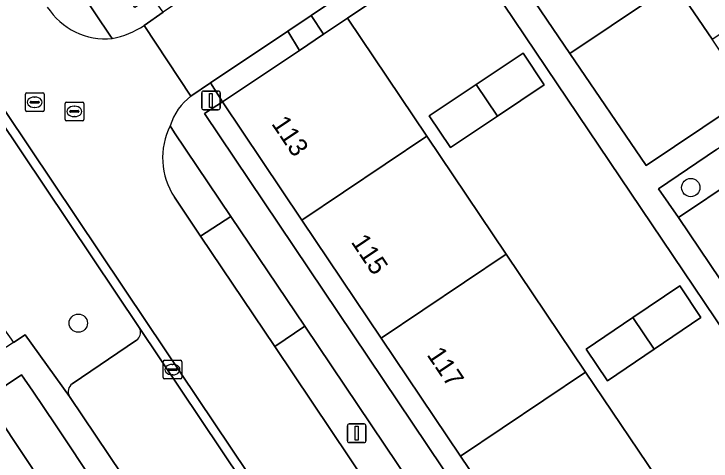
# Model space of a CAD drawing. Extents: x 158793 to 159888, y 384317 to 385256.
# Drawn here: x 159136.27 to 159173.56, y 384652.42 to 384676.36 of the extents above; entities that cross this region are included whole.
import ezdxf

# ---------------------------------------------------------------- set-up
doc = ezdxf.new("R2010")
doc.units = 0
for name, color, linetype in [('IMGEO_Berm_groen', 7, 'Continuous'), ('IMGEO_Boom', 7, 'Continuous'), ('IMGEO_Erf', 7, 'Continuous'), ('IMGEO_Groenvoorziening', 7, 'Continuous'), ('IMGEO_Kolk', 7, 'Continuous'), ('IMGEO_Lichtmast', 7, 'Continuous'), ('IMGEO_Pand', 7, 'Continuous'), ('IMGEO_Pand_nummerreeks', 7, 'Continuous'), ('IMGEO_Parkeervlak_halfverhard', 7, 'Continuous'), ('IMGEO_Parkeervlak_open', 7, 'Continuous'), ('IMGEO_Rijbaan_lokaal_open', 7, 'Continuous'), ('IMGEO_Rioolput', 7, 'Continuous'), ('IMGEO_Voetpad_open', 7, 'Continuous')]:
    doc.layers.add(name, color=color, linetype=linetype)

msp = doc.modelspace()

# ---------------------------------------------------------------- linework, layer by layer
at = {"layer": 'IMGEO_Berm_groen'}
for points in [[(159141.53, 384675.048), (159141.397, 384675.222), (159125.586, 384698.761)], [(159127.995, 384675.679), (159126.599, 384674.78), (159125.549, 384674.076), (159126.206, 384673.075), (159128.775, 384674.779), (159130.148, 384672.707), (159127.589, 384671.004), (159136.246, 384658.77), (159136.871, 384659.186), (159139.241, 384655.885)], [(159143.015, 384659.487), (159142.977, 384659.569), (159132.904, 384674.594)], [(159144.861, 384670.004), (159144.633, 384670.379)], [(159144.859, 384666.556), (159146.259, 384664.469), (159147.882, 384665.51), (159144.861, 384670.004)], [(159151.826, 384659.643), (159150.227, 384658.552), (159167.157, 384633.31)], [(159170.662, 384631.666), (159170.315, 384632.138), (159151.826, 384659.643)], [(159139.387, 384656.562), (159142.831, 384658.894)]]:
    msp.add_lwpolyline(points, dxfattribs=at)
for centre, radius, start, end in [((159141.175, 384678.74), 3.709, 212.7786, 275.4984), ((159148.052, 384668.663), 3.826, 153.3489, 213.4175), ((159142.536, 384659.311), 0.51, 305.2924, 20.2307), ((159139.7, 384656.14), 0.525, 126.5692, 209.091)]:
    msp.add_arc(centre, radius, start, end, dxfattribs=at)
at = {"layer": 'IMGEO_Boom'}
for centre in [(159172.479, 384667.067), (159139.714, 384659.808)]:
    msp.add_circle(centre, 0.489, dxfattribs=at)
at = {"layer": 'IMGEO_Erf'}
for points in [[(159193.99, 384675.621), (159189.711, 384681.984), (159196.396, 384686.477), (159192.579, 384692.111), (159185.929, 384687.638), (159179.282, 384683.167), (159172.635, 384678.697), (159166.005, 384674.237), (159170.09, 384668.243), (159183.846, 384677.493), (159200.696, 384652.438), (159206.826, 384656.531), (159202.548, 384662.893), (159198.269, 384669.257)], [(159160.216, 384680.233), (159154.114, 384676.135), (159158.36, 384669.818), (159162.607, 384663.5), (159166.854, 384657.182), (159171.101, 384650.864), (159175.348, 384644.546), (159179.596, 384638.227), (159185.666, 384642.429)], [(159176.993, 384673.63), (159175.3, 384672.493), (159173.617, 384675.003), (159171.935, 384677.512), (159173.629, 384678.648), (159175.311, 384676.139)], [(159162.134, 384670.885), (159159.624, 384669.204), (159158.489, 384670.899), (159160.999, 384672.58), (159163.508, 384674.261), (159164.643, 384672.566)], [(159168.023, 384656.723), (159166.88, 384658.408), (159169.384, 384660.105), (159171.887, 384661.802), (159173.015, 384660.108), (159170.526, 384658.42)]]:
    msp.add_lwpolyline(points, close=True, dxfattribs=at)
msp.add_lwpolyline([(159118.838, 384624.921), (159110.182, 384637.924), (159135.451, 384654.745), (159139.092, 384649.275), (159139.909, 384649.828), (159141.021, 384650.58), (159140.693, 384651.069), (159138.492, 384654.363), (159137.276, 384656.161), (159136.677, 384657.042), (159107.897, 384637.647), (159125.656, 384610.969)], dxfattribs=at)
at = {"layer": 'IMGEO_Groenvoorziening'}
for points in [[(159160.216, 384680.233), (159159.55, 384681.239), (159152.18, 384676.285), (159152.829, 384675.272), (159154.114, 384676.135)], [(159151.548, 384674.412), (159150.917, 384675.437), (159146.794, 384672.665), (159147.433, 384671.648)]]:
    msp.add_lwpolyline(points, close=True, dxfattribs=at)
msp.add_lwpolyline([(159173.849, 384669.112), (159170.75, 384666.999), (159171.817, 384665.462), (159174.9, 384667.527)], dxfattribs=at)
at = {"layer": 'IMGEO_Kolk'}
for p, q in [((159144.254, 384656.893), (159144.254, 384657.745)), ((159144.329, 384657.819), (159145.181, 384657.819)), ((159145.255, 384657.745), (159145.255, 384656.893)), ((159144.513, 384657.313), (159144.513, 384657.325)), ((159144.951, 384657.276), (159144.553, 384657.276)), ((159144.556, 384657.362), (159144.954, 384657.362)), ((159144.742, 384657.599), (159144.767, 384657.599)), ((159144.997, 384657.325), (159144.997, 384657.313)), ((159144.765, 384657.039), (159144.74, 384657.039)), ((159145.181, 384656.819), (159144.329, 384656.819))]:
    msp.add_line(p, q, dxfattribs=at)
for points in [[(159144.254, 384656.893), (159144.254, 384657.745)], [(159144.329, 384657.819), (159145.181, 384657.819)], [(159145.255, 384657.745), (159145.255, 384656.893)], [(159145.181, 384656.819), (159144.329, 384656.819)]]:
    msp.add_lwpolyline(points, dxfattribs=at)
for centre, radius, start, end in [((159144.331, 384657.743), 0.0765, 91.552, 178.448), ((159144.331, 384657.743), 0.0765, 91.552, 178.448), ((159145.179, 384657.743), 0.0765, 1.552, 88.448), ((159145.179, 384657.743), 0.0765, 1.552, 88.448), ((159144.553, 384657.322), 0.0403, 85.8775, 175.7526), ((159144.55, 384657.312), 0.0366, 178.938, 274.7102), ((159144.954, 384657.319), 0.043, 264.8664, 352.4533), ((159144.958, 384657.324), 0.0386, 1.7309, 96.639), ((159144.331, 384656.895), 0.0765, 181.552, 268.448), ((159144.331, 384656.895), 0.0765, 181.552, 268.448), ((159145.179, 384656.895), 0.0765, 271.552, 358.448), ((159145.179, 384656.895), 0.0765, 271.552, 358.448)]:
    msp.add_arc(centre, radius, start, end, dxfattribs=at)
for centre, major_axis, ratio, start_param, end_param in [((159144.741, 384657.319), (-0.387, 0.002), 0.722429, 4.712389, 7.853982), ((159144.766, 384657.319), (-0.39, 0.002), 0.717154, 1.570796, 4.712389)]:
    msp.add_ellipse(centre, major_axis=major_axis, ratio=ratio, start_param=start_param, end_param=end_param, dxfattribs=at)
at = {"layer": 'IMGEO_Lichtmast'}
for p, q in [((159146.416, 384672.232), (159147.206, 384672.232)), ((159147.206, 384672.232), (159146.416, 384672.232)), ((159146.316, 384671.332), (159146.316, 384672.132)), ((159146.316, 384672.132), (159146.316, 384671.332)), ((159147.306, 384672.132), (159147.306, 384671.332)), ((159147.306, 384671.332), (159147.306, 384672.132)), ((159147.206, 384671.232), (159146.416, 384671.232)), ((159146.416, 384671.232), (159147.206, 384671.232)), ((159154.113, 384653.512), (159154.113, 384654.312)), ((159154.113, 384654.312), (159154.113, 384653.512)), ((159154.213, 384654.412), (159155.003, 384654.412)), ((159155.003, 384654.412), (159154.213, 384654.412)), ((159155.103, 384654.312), (159155.103, 384653.512)), ((159155.103, 384653.512), (159155.103, 384654.312)), ((159155.003, 384653.412), (159154.213, 384653.412)), ((159154.213, 384653.412), (159155.003, 384653.412))]:
    msp.add_line(p, q, dxfattribs=at)
for points in [[(159146.736, 384672.107), (159146.886, 384672.107), (159146.886, 384671.357), (159146.736, 384671.357), (159146.736, 384672.107)], [(159154.533, 384654.287), (159154.683, 384654.287), (159154.683, 384653.537), (159154.533, 384653.537), (159154.533, 384654.287)]]:
    msp.add_lwpolyline(points, dxfattribs=at)
for centre, start, end in [((159146.416, 384672.132), 90, 180), ((159146.416, 384672.132), 90, 180), ((159147.206, 384672.132), 0, 90), ((159147.206, 384672.132), 360, 90), ((159146.416, 384671.332), 180, 270), ((159146.416, 384671.332), 180, 270), ((159147.206, 384671.332), 270, 0), ((159147.206, 384671.332), 270, 0), ((159154.213, 384654.312), 90, 180), ((159154.213, 384654.312), 90, 180), ((159155.003, 384654.312), 0, 90), ((159155.003, 384654.312), 360, 90), ((159154.213, 384653.512), 180, 270), ((159154.213, 384653.512), 180, 270), ((159155.003, 384653.512), 270, 0), ((159155.003, 384653.512), 270, 0)]:
    msp.add_arc(centre, 0.1, start, end, dxfattribs=at)
at = {"layer": 'IMGEO_Pand'}
for points in [[(159168.046, 384685.528), (159161.396, 384681.061), (159166.005, 384674.237), (159172.635, 384678.697)], [(159173.629, 384678.648), (159171.935, 384677.512), (159173.617, 384675.003), (159175.311, 384676.139)], [(159154.114, 384676.135), (159152.829, 384675.272), (159151.548, 384674.412), (159147.433, 384671.648), (159151.678, 384665.329), (159158.36, 384669.818)], [(159164.643, 384672.566), (159163.508, 384674.261), (159160.999, 384672.58), (159162.134, 384670.885)], [(159162.134, 384670.885), (159160.999, 384672.58), (159158.489, 384670.899), (159159.624, 384669.204)], [(159158.36, 384669.818), (159151.678, 384665.329), (159155.924, 384659.01), (159162.607, 384663.5)], [(159162.607, 384663.5), (159155.924, 384659.01), (159160.169, 384652.691), (159166.854, 384657.182)], [(159171.887, 384661.802), (159169.384, 384660.105), (159170.526, 384658.42), (159173.015, 384660.108)], [(159169.384, 384660.105), (159166.88, 384658.408), (159168.023, 384656.723), (159170.526, 384658.42)], [(159166.854, 384657.182), (159160.169, 384652.691), (159164.414, 384646.371), (159171.101, 384650.864)], [(159144.107, 384641.742), (159140.454, 384647.229), (159139.092, 384649.275), (159135.451, 384654.745), (159110.182, 384637.924), (159118.838, 384624.921)]]:
    msp.add_lwpolyline(points, close=True, dxfattribs=at)
at = {"layer": 'IMGEO_Parkeervlak_halfverhard'}
msp.add_lwpolyline([(159147.882, 384665.51), (159146.259, 384664.469), (159150.227, 384658.552), (159151.826, 384659.643)], close=True, dxfattribs=at)
at = {"layer": 'IMGEO_Parkeervlak_open'}
for points in [[(159174.9, 384667.527), (159171.817, 384665.462), (159179.041, 384654.743), (159182.119, 384656.825)], [(159142.977, 384659.569), (159143.015, 384659.487)], [(159151.786, 384646.421), (159142.977, 384659.569)], [(159142.831, 384658.894), (159139.387, 384656.562)], [(159139.241, 384655.885), (159146.994, 384644.33)]]:
    msp.add_lwpolyline(points, dxfattribs=at)
for centre, radius, start, end in [((159142.536, 384659.311), 0.51, 305.2924, 20.2307), ((159139.7, 384656.14), 0.525, 126.5692, 209.091)]:
    msp.add_arc(centre, radius, start, end, dxfattribs=at)
at = {"layer": 'IMGEO_Rijbaan_lokaal_open'}
for points in [[(159161.494, 384687.533), (159158.406, 384685.425), (159158.127, 384685.847), (159156.889, 384685.009), (159149.027, 384679.686), (159147.747, 384678.819), (159144.25, 384676.451), (159143.234, 384675.735), (159145.743, 384671.966), (159146.794, 384672.665), (159150.917, 384675.437), (159152.18, 384676.285), (159159.55, 384681.239), (159187.338, 384699.918), (159184.8, 384703.767), (159172.11, 384695.307), (159170.84, 384694.46), (159171.159, 384693.985), (159168.011, 384691.91)], [(159145.743, 384671.966), (159143.234, 384675.735)], [(159169.474, 384620.932), (159143.376, 384659.836), (159133.301, 384674.864)], [(159133.301, 384674.864), (159143.376, 384659.836), (159169.474, 384620.932)], [(159132.904, 384674.594), (159142.977, 384659.569), (159151.786, 384646.421), (159151.816, 384646.386), (159153.659, 384643.618), (159153.675, 384643.594), (159162.493, 384630.457), (159163.415, 384629.083), (159169.136, 384620.552)], [(159167.157, 384633.31), (159150.227, 384658.552), (159146.259, 384664.469), (159144.859, 384666.556)]]:
    msp.add_lwpolyline(points, dxfattribs=at)
for centre, radius, start, end in [((159141.175, 384678.74), 3.709, 212.7786, 275.4984), ((159140.604, 384679.802), 4.843, 281.0239, 302.8917), ((159147.74, 384669.387), 3.262, 127.7599, 162.2996), ((159148.052, 384668.663), 3.826, 153.3489, 213.4175)]:
    msp.add_arc(centre, radius, start, end, dxfattribs=at)
at = {"layer": 'IMGEO_Rioolput'}
for p, q in [((159136.885, 384671.207), (159136.885, 384672.059)), ((159136.96, 384672.133), (159137.812, 384672.133)), ((159137.373, 384671.913), (159137.398, 384671.913)), ((159137.886, 384672.059), (159137.886, 384671.207)), ((159137.144, 384671.627), (159137.144, 384671.639)), ((159137.582, 384671.59), (159137.184, 384671.59)), ((159137.187, 384671.676), (159137.585, 384671.676)), ((159137.628, 384671.639), (159137.628, 384671.627)), ((159139.007, 384670.716), (159139.007, 384671.568)), ((159139.082, 384671.642), (159139.934, 384671.642)), ((159140.008, 384671.568), (159140.008, 384670.716)), ((159137.812, 384671.133), (159136.96, 384671.133)), ((159137.396, 384671.353), (159137.371, 384671.353)), ((159139.266, 384671.136), (159139.266, 384671.148)), ((159139.704, 384671.099), (159139.306, 384671.099)), ((159139.309, 384671.185), (159139.707, 384671.185)), ((159139.495, 384671.422), (159139.52, 384671.422)), ((159139.75, 384671.148), (159139.75, 384671.136)), ((159139.518, 384670.862), (159139.493, 384670.862)), ((159139.934, 384670.642), (159139.082, 384670.642))]:
    msp.add_line(p, q, dxfattribs=at)
for points in [[(159136.885, 384671.207), (159136.885, 384672.059)], [(159136.96, 384672.133), (159137.812, 384672.133)], [(159137.886, 384672.059), (159137.886, 384671.207)], [(159139.007, 384670.716), (159139.007, 384671.568)], [(159139.082, 384671.642), (159139.934, 384671.642)], [(159140.008, 384671.568), (159140.008, 384670.716)], [(159137.812, 384671.133), (159136.96, 384671.133)], [(159139.934, 384670.642), (159139.082, 384670.642)]]:
    msp.add_lwpolyline(points, dxfattribs=at)
for centre, radius, start, end in [((159136.962, 384672.057), 0.0765, 91.552, 178.448), ((159136.962, 384672.057), 0.0765, 91.552, 178.448), ((159137.81, 384672.057), 0.0765, 1.552, 88.448), ((159137.81, 384672.057), 0.0765, 1.552, 88.448), ((159137.184, 384671.636), 0.0403, 85.8775, 175.7526), ((159137.181, 384671.626), 0.0366, 178.938, 274.7102), ((159137.585, 384671.633), 0.043, 264.8664, 352.4533), ((159137.589, 384671.638), 0.0386, 1.7309, 96.639), ((159139.084, 384671.566), 0.0765, 91.552, 178.448), ((159139.084, 384671.566), 0.0765, 91.552, 178.448), ((159139.932, 384671.566), 0.0765, 1.552, 88.448), ((159139.932, 384671.566), 0.0765, 1.552, 88.448), ((159136.962, 384671.209), 0.0765, 181.552, 268.448), ((159136.962, 384671.209), 0.0765, 181.552, 268.448), ((159137.81, 384671.209), 0.0765, 271.552, 358.448), ((159137.81, 384671.209), 0.0765, 271.552, 358.448), ((159139.306, 384671.145), 0.0403, 85.8775, 175.7526), ((159139.303, 384671.135), 0.0366, 178.938, 274.7102), ((159139.707, 384671.142), 0.043, 264.8664, 352.4533), ((159139.711, 384671.147), 0.0386, 1.7309, 96.639), ((159139.084, 384670.718), 0.0765, 181.552, 268.448), ((159139.084, 384670.718), 0.0765, 181.552, 268.448), ((159139.932, 384670.718), 0.0765, 271.552, 358.448), ((159139.932, 384670.718), 0.0765, 271.552, 358.448)]:
    msp.add_arc(centre, radius, start, end, dxfattribs=at)
for centre, major_axis, ratio, start_param, end_param in [((159137.372, 384671.633), (-0.387, 0.002), 0.722429, 4.712389, 7.853982), ((159137.397, 384671.633), (-0.39, 0.002), 0.717154, 1.570796, 4.712389), ((159139.494, 384671.142), (-0.387, 0.002), 0.722429, 4.712389, 7.853982), ((159139.519, 384671.142), (-0.39, 0.002), 0.717154, 1.570796, 4.712389)]:
    msp.add_ellipse(centre, major_axis=major_axis, ratio=ratio, start_param=start_param, end_param=end_param, dxfattribs=at)
at = {"layer": 'IMGEO_Voetpad_open'}
for points in [[(159143.234, 384675.735), (159144.25, 384676.451), (159143.648, 384677.306), (159142.742, 384676.698), (159117.11, 384714.557)], [(159113.6, 384713.295), (159115.157, 384714.276), (159117.976, 384710.09), (159121.876, 384704.284), (159125.586, 384698.761), (159141.397, 384675.222), (159141.53, 384675.048)], [(159200.696, 384652.438), (159183.846, 384677.493), (159170.09, 384668.243), (159166.005, 384674.237), (159161.396, 384681.061)], [(159160.216, 384680.233), (159185.666, 384642.429), (159186.31, 384641.472), (159187.415, 384642.245), (159185.923, 384644.473), (159180.087, 384653.183), (159179.041, 384654.743), (159171.817, 384665.462), (159170.75, 384666.999), (159173.849, 384669.112), (159180.372, 384673.489), (159180.426, 384673.525), (159183.515, 384675.584), (159184.572, 384674.044), (159190.373, 384665.384), (159191.394, 384663.8), (159198.595, 384653.134)], [(159146.474, 384671.034), (159147.433, 384671.648), (159146.794, 384672.665), (159145.743, 384671.966)], [(159172.532, 384632.201), (159173.51, 384632.864), (159172.905, 384633.733), (159171.93, 384633.091), (159146.474, 384671.034)], [(159144.633, 384670.379), (159144.861, 384670.004), (159147.882, 384665.51), (159151.826, 384659.643), (159170.315, 384632.138), (159170.662, 384631.666)], [(159146.994, 384644.33), (159139.241, 384655.885), (159136.871, 384659.186), (159136.246, 384658.77), (159135.895, 384658.537), (159130.835, 384655.176), (159130.227, 384654.776), (159126.067, 384652.043), (159125.846, 384651.898), (159116.728, 384645.734), (159116.293, 384645.434), (159112.174, 384642.595), (159111.78, 384642.323), (159106.798, 384638.971), (159096.373, 384654.502), (159094.647, 384653.405), (159095.283, 384652.499), (159098.017, 384648.608), (159104.422, 384639.047), (159106.149, 384636.469), (159107.897, 384637.647), (159136.677, 384657.042)], [(159136.677, 384657.042), (159137.276, 384656.161), (159138.492, 384654.363), (159140.693, 384651.069), (159141.021, 384650.58), (159142.385, 384648.546), (159146.044, 384643.093), (159146.077, 384643.044), (159148.35, 384639.651), (159154.621, 384630.291), (159153.662, 384629.631), (159153.037, 384629.217), (159152.616, 384628.959), (159151.902, 384628.484), (159152.688, 384627.303), (159154.724, 384628.639), (159155.435, 384629.138), (159157.911, 384625.402), (159163.415, 384629.083), (159162.493, 384630.457), (159162.433, 384630.524)]]:
    msp.add_lwpolyline(points, dxfattribs=at)
for points in [[(159152.18, 384676.285), (159150.917, 384675.437), (159151.548, 384674.412), (159152.829, 384675.272)], [(159160.169, 384652.691), (159155.924, 384659.01), (159151.678, 384665.329), (159147.433, 384671.648), (159146.474, 384671.034), (159171.93, 384633.091), (159172.905, 384633.733), (159168.66, 384640.052), (159164.414, 384646.371)]]:
    msp.add_lwpolyline(points, close=True, dxfattribs=at)
for centre, radius, start, end in [((159140.604, 384679.802), 4.843, 281.0239, 302.8917), ((159147.74, 384669.387), 3.262, 127.7599, 162.2996)]:
    msp.add_arc(centre, radius, start, end, dxfattribs=at)

# ---------------------------------------------------------------- texts
at = {"layer": 'IMGEO_Pand_nummerreeks'}
for s, p in [('113', (159150.019, 384670.488)), ('115', (159154.274, 384664.155)), ('117', (159158.33, 384658.117))]:
    msp.add_text(s, height=1, rotation=303.896, dxfattribs=at).set_placement(p)

doc.saveas('drawing.dxf')
